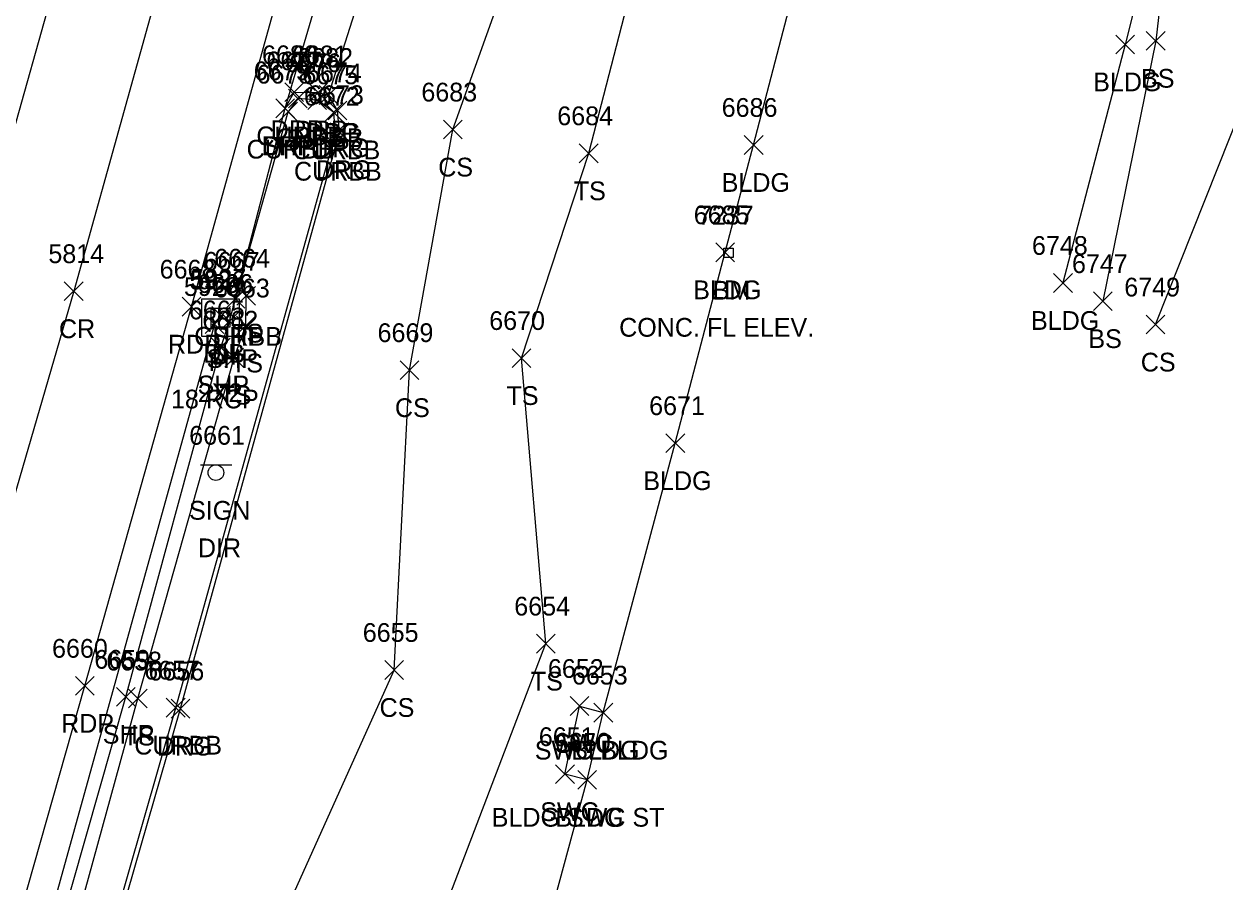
# Model space of a CAD drawing. Extents: x 1443912 to 1445411, y 621446 to 623693.
# Drawn here: x 1444716.8 to 1444844.8, y 622412.7 to 622504.3 of the extents above; entities that cross this region are included whole.
import ezdxf

# ---------------------------------------------------------------- set-up
doc = ezdxf.new("R2010")
doc.units = 0
for name, color, linetype in [('C_A', 7, 'Continuous'), ('C_I', 7, 'Continuous'), ('CPBM', 7, 'Continuous'), ('D_A', 7, 'Continuous'), ('D_C', 7, 'Continuous'), ('D_I', 7, 'Continuous'), ('D_TIC', 7, 'Continuous'), ('DCP', 7, 'Continuous'), ('DS', 7, 'Continuous'), ('L_A', 7, 'Continuous'), ('L_C', 7, 'Continuous'), ('L_I', 7, 'Continuous'), ('L_TIC', 7, 'Continuous'), ('LBC', 7, 'Continuous'), ('LELB', 7, 'Continuous'), ('P_A', 7, 'Continuous'), ('P_I', 7, 'Continuous'), ('P_TIC', 7, 'Continuous'), ('PET', 7, 'Continuous'), ('PRC', 7, 'Continuous'), ('PSP', 7, 'Continuous'), ('R_A', 7, 'Continuous'), ('R_I', 7, 'Continuous'), ('R_TIC', 7, 'Continuous'), ('RC', 7, 'Continuous'), ('RDG', 7, 'Continuous'), ('RDP', 7, 'Continuous'), ('RSW', 7, 'Continuous'), ('S_A', 7, 'Continuous'), ('S_C', 7, 'Continuous'), ('S_I', 7, 'Continuous'), ('SSGN', 7, 'Continuous')]:
    doc.layers.add(name, color=color, linetype=linetype)

msp = doc.modelspace()

# ---------------------------------------------------------------- linework, layer by layer
at = {"layer": 'CPBM'}
for p, q in [((1444791.48, 622479.37), (1444791.48, 622480.37)), ((1444791.48, 622480.37), (1444792.48, 622480.37)), ((1444791.98, 622479.87), (1444791.98, 622479.87)), ((1444791.98, 622479.87), (1444791.98, 622479.87)), ((1444792.48, 622480.37), (1444792.48, 622479.37)), ((1444792.48, 622479.37), (1444791.48, 622479.37))]:
    msp.add_line(p, q, dxfattribs=at)
at = {"layer": 'D_TIC'}
for points in [[(1444736.85, 622472.13), (1444738.85, 622474.13)], [(1444738.85, 622472.13), (1444736.85, 622474.13)], [(1444736.15, 622471.26), (1444738.15, 622473.26)], [(1444738.15, 622471.26), (1444736.15, 622473.26)]]:
    msp.add_lwpolyline(points, dxfattribs=at)
at = {"layer": 'DCP'}
msp.add_lwpolyline([(1444737.15, 622472.26), (1444683.32, 622278.32)], dxfattribs=at)
at = {"layer": 'DS'}
for p, q in [((1444735.8, 622474.94), (1444739.8, 622474.94)), ((1444735.8, 622470.94), (1444735.8, 622474.94)), ((1444739.8, 622474.94), (1444739.8, 622470.94)), ((1444736.8, 622471.94), (1444736.8, 622473.94)), ((1444736.8, 622473.94), (1444738.8, 622473.94)), ((1444738.8, 622473.94), (1444738.8, 622471.94)), ((1444737.81, 622472.94), (1444737.81, 622472.94)), ((1444737.81, 622472.94), (1444737.81, 622472.94)), ((1444739.8, 622470.94), (1444735.8, 622470.94)), ((1444738.8, 622471.94), (1444736.8, 622471.94))]:
    msp.add_line(p, q, dxfattribs=at)
at = {"layer": 'L_TIC'}
for points in [[(1444833.3, 622501.09), (1444835.3, 622503.09)], [(1444835.3, 622501.09), (1444833.3, 622503.09)], [(1444836.56, 622501.47), (1444838.56, 622503.47)], [(1444838.56, 622501.47), (1444836.56, 622503.47)], [(1444761.58, 622492), (1444763.58, 622494)], [(1444763.58, 622492), (1444761.58, 622494)], [(1444776.07, 622489.47), (1444778.07, 622491.47)], [(1444778.07, 622489.47), (1444776.07, 622491.47)], [(1444793.67, 622490.36), (1444795.67, 622492.36)], [(1444795.67, 622490.36), (1444793.67, 622492.36)], [(1444790.63, 622478.91), (1444792.63, 622480.91)], [(1444792.63, 622478.91), (1444790.63, 622480.91)], [(1444826.67, 622475.64), (1444828.67, 622477.64)], [(1444828.67, 622475.64), (1444826.67, 622477.64)], [(1444739.52, 622474.28), (1444741.52, 622476.28)], [(1444741.52, 622474.28), (1444739.52, 622476.28)], [(1444830.93, 622473.7), (1444832.93, 622475.7)], [(1444832.93, 622473.7), (1444830.93, 622475.7)], [(1444739.51, 622471.1), (1444741.51, 622473.1)], [(1444741.51, 622471.1), (1444739.51, 622473.1)], [(1444836.53, 622471.2), (1444838.53, 622473.2)], [(1444838.53, 622471.2), (1444836.53, 622473.2)], [(1444738.26, 622467.67), (1444740.26, 622469.67)], [(1444740.26, 622467.67), (1444738.26, 622469.67)], [(1444768.9, 622467.63), (1444770.9, 622469.63)], [(1444770.9, 622467.63), (1444768.9, 622469.63)], [(1444756.96, 622466.34), (1444758.96, 622468.34)], [(1444758.96, 622466.34), (1444756.96, 622468.34)], [(1444785.31, 622458.55), (1444787.31, 622460.55)], [(1444787.31, 622458.55), (1444785.31, 622460.55)], [(1444771.49, 622437.17), (1444773.49, 622439.17)], [(1444773.49, 622437.17), (1444771.49, 622439.17)], [(1444755.32, 622434.36), (1444757.32, 622436.36)], [(1444757.32, 622434.36), (1444755.32, 622436.36)], [(1444727.96, 622431.31), (1444729.96, 622433.31)], [(1444729.96, 622431.31), (1444727.96, 622433.31)], [(1444777.63, 622429.81), (1444779.63, 622431.81)], [(1444779.63, 622429.81), (1444777.63, 622431.81)], [(1444775.91, 622422.65), (1444777.91, 622424.65)], [(1444777.91, 622422.65), (1444775.91, 622424.65)]]:
    msp.add_lwpolyline(points, dxfattribs=at)
at = {"layer": 'LBC'}
msp.add_lwpolyline([(1444792.62, 622344.51), (1444758.25, 622353.56), (1444766.9, 622386.76), (1444776.91, 622423.65), (1444778.63, 622430.81), (1444786.31, 622459.55), (1444791.63, 622479.91), (1444794.67, 622491.36), (1444803.27, 622524.38), (1444837.65, 622515.4), (1444834.3, 622502.09), (1444827.67, 622476.64)], dxfattribs=at)
at = {"layer": 'LELB'}
for points in [[(1444744.93, 622339.22), (1444745.5, 622357.06), (1444753.17, 622387.48), (1444772.49, 622438.17), (1444769.9, 622468.63), (1444777.07, 622490.47), (1444785.46, 622522.85), (1444790.77, 622543.67), (1444811.19, 622567.84), (1444821.42, 622569.11), (1444823.99, 622546.92), (1444828.15, 622535.05)], [(1444742.88, 622284.71), (1444748.75, 622311.2), (1444753.94, 622334.73), (1444744.93, 622339.22), (1444726.6, 622359.05), (1444735.05, 622388.08), (1444756.32, 622435.36), (1444757.96, 622467.34), (1444762.58, 622493), (1444774.84, 622527.33), (1444774.74, 622549.75)], [(1444837.37, 622518.31), (1444839.05, 622515.22), (1444837.56, 622502.47), (1444831.93, 622474.7)], [(1444837.53, 622472.2), (1444848.13, 622498.83), (1444853.79, 622477.95)], [(1444739.97, 622249.43), (1444721.46, 622251.74), (1444700.92, 622255.52), (1444690.61, 622258.05), (1444683.65, 622264.07), (1444685.55, 622270.32), (1444689.9, 622281.11), (1444696.48, 622313.23), (1444707.7, 622344.5), (1444714.14, 622363.56), (1444716.18, 622385.71), (1444728.96, 622432.31), (1444739.26, 622468.67), (1444740.51, 622472.1), (1444740.52, 622475.28)]]:
    msp.add_lwpolyline(points, dxfattribs=at)
at = {"layer": 'P_TIC'}
for points in [[(1444743.7, 622494.27), (1444745.7, 622496.27)], [(1444745.7, 622494.27), (1444743.7, 622496.27)], [(1444721.13, 622474.76), (1444723.13, 622476.76)], [(1444723.13, 622474.76), (1444721.13, 622476.76)], [(1444733.7, 622473.11), (1444735.7, 622475.11)], [(1444735.7, 622473.11), (1444733.7, 622475.11)], [(1444738.4, 622473.95), (1444740.4, 622475.95)], [(1444740.4, 622473.95), (1444738.4, 622475.95)], [(1444737.76, 622471.58), (1444739.76, 622473.58)], [(1444739.76, 622471.58), (1444737.76, 622473.58)], [(1444736.82, 622468.76), (1444738.82, 622470.76)], [(1444738.82, 622468.76), (1444736.82, 622470.76)], [(1444722.31, 622432.67), (1444724.31, 622434.67)], [(1444724.31, 622432.67), (1444722.31, 622434.67)], [(1444726.7, 622431.5), (1444728.7, 622433.5)], [(1444728.7, 622431.5), (1444726.7, 622433.5)]]:
    msp.add_lwpolyline(points, dxfattribs=at)
at = {"layer": 'PET'}
msp.add_lwpolyline([(1444623.48, 622089.5), (1444632.2, 622118.09), (1444643.37, 622155.41), (1444656.28, 622199.74), (1444664.4, 622229.62), (1444679.43, 622278.16), (1444690.09, 622315.58), (1444698.44, 622345.72), (1444710.36, 622388.15), (1444723.31, 622433.67), (1444734.7, 622474.11), (1444754.07, 622543.94), (1444762.27, 622574.66), (1444773.16, 622611.58)], dxfattribs=at)
at = {"layer": 'PRC'}
for points in [[(1444864.1, 623005.34), (1444851.39, 622950.16), (1444837.25, 622893.61), (1444822.84, 622838.02), (1444810.34, 622792.94), (1444799.32, 622750.35), (1444788.05, 622712.65), (1444779.51, 622680.27), (1444771.55, 622651.63), (1444762.01, 622615.65), (1444752.75, 622584.12), (1444739.92, 622538.84), (1444733.6, 622516.91), (1444722.13, 622475.76), (1444713.59, 622446.41), (1444702.09, 622404.55), (1444689.87, 622361.08), (1444676.17, 622311.92), (1444657.59, 622249.98), (1444643.66, 622204.01), (1444635.38, 622177.66), (1444620.59, 622126.88), (1444604.97, 622075.74)], [(1444846.73, 622950.74), (1444829.37, 622896.11), (1444814.12, 622840.53), (1444801.7, 622795.63), (1444790.08, 622753.54), (1444778.65, 622716.11), (1444769.12, 622683.18), (1444760.94, 622654.81), (1444750.77, 622619.03), (1444741.67, 622586.01), (1444729.73, 622541.23), (1444723.42, 622520.39), (1444711.77, 622478.97), (1444703.65, 622449.63), (1444691.66, 622407.43), (1444679.51, 622365.85), (1444664.93, 622313.64), (1444649.43, 622253.98), (1444637.04, 622206.21), (1444631.31, 622178.74), (1444618.32, 622127.38), (1444604.97, 622075.74)]]:
    msp.add_lwpolyline(points, dxfattribs=at)
at = {"layer": 'PSP'}
msp.add_lwpolyline([(1444628.13, 622076.36), (1444639.3, 622115.36), (1444644.89, 622137.62), (1444649.21, 622153.55), (1444661.8, 622198.05), (1444670.3, 622227.5), (1444674.58, 622242.76), (1444679.89, 622261.63), (1444684.08, 622277.6), (1444693.94, 622313.61), (1444703.2, 622344.72), (1444709.19, 622365.83), (1444714.84, 622387.4), (1444727.7, 622432.5), (1444737.82, 622469.76), (1444738.76, 622472.58), (1444739.4, 622474.95), (1444744.7, 622495.27), (1444757.04, 622537.24), (1444773.11, 622588.76)], dxfattribs=at)
at = {"layer": 'R_TIC'}
for points in [[(1444744.66, 622495.98), (1444746.66, 622497.98)], [(1444746.66, 622495.98), (1444744.66, 622497.98)], [(1444747.21, 622495.96), (1444749.21, 622497.96)], [(1444749.21, 622495.96), (1444747.21, 622497.96)], [(1444745.03, 622495.33), (1444747.03, 622497.33)], [(1444747.03, 622495.33), (1444745.03, 622497.33)], [(1444747.11, 622495.13), (1444749.11, 622497.13)], [(1444749.11, 622495.13), (1444747.11, 622497.13)], [(1444748.33, 622495.69), (1444750.33, 622497.69)], [(1444750.33, 622495.69), (1444748.33, 622497.69)], [(1444748.33, 622495.69), (1444750.33, 622497.69)], [(1444750.33, 622495.69), (1444748.33, 622497.69)], [(1444743.7, 622494.27), (1444745.7, 622496.27)], [(1444745.7, 622494.27), (1444743.7, 622496.27)], [(1444744, 622493.91), (1444746, 622495.91)], [(1444746, 622493.91), (1444744, 622495.91)], [(1444744, 622493.91), (1444746, 622495.91)], [(1444746, 622493.91), (1444744, 622495.91)], [(1444748.88, 622493.84), (1444750.88, 622495.84)], [(1444750.88, 622493.84), (1444748.88, 622495.84)], [(1444749.28, 622494.05), (1444751.28, 622496.05)], [(1444751.28, 622494.05), (1444749.28, 622496.05)], [(1444749.05, 622491.56), (1444751.05, 622493.56)], [(1444751.05, 622491.56), (1444749.05, 622493.56)], [(1444749.49, 622491.72), (1444751.49, 622493.72)], [(1444751.49, 622491.72), (1444749.49, 622493.72)], [(1444738.4, 622473.95), (1444740.4, 622475.95)], [(1444740.4, 622473.95), (1444738.4, 622475.95)], [(1444775.08, 622430.52), (1444777.08, 622432.52)], [(1444777.08, 622430.52), (1444775.08, 622432.52)], [(1444732.01, 622430.34), (1444734.01, 622432.34)], [(1444734.01, 622430.34), (1444732.01, 622432.34)], [(1444732.52, 622430.24), (1444734.52, 622432.24)], [(1444734.52, 622430.24), (1444732.52, 622432.24)], [(1444777.63, 622429.81), (1444779.63, 622431.81)], [(1444779.63, 622429.81), (1444777.63, 622431.81)], [(1444773.54, 622423.25), (1444775.54, 622425.25)], [(1444775.54, 622423.25), (1444773.54, 622425.25)], [(1444775.91, 622422.65), (1444777.91, 622424.65)], [(1444777.91, 622422.65), (1444775.91, 622424.65)]]:
    msp.add_lwpolyline(points, dxfattribs=at)
at = {"layer": 'RC'}
for points in [[(1444717.51, 622384.77), (1444720.96, 622389.26), (1444733.01, 622431.34), (1444750.05, 622492.56), (1444749.88, 622494.84), (1444748.11, 622496.13), (1444746.03, 622496.33), (1444745, 622494.91)], [(1444739.4, 622474.95), (1444745, 622494.91)]]:
    msp.add_lwpolyline(points, dxfattribs=at)
at = {"layer": 'RDG'}
msp.add_lwpolyline([(1444714.84, 622387.4), (1444716.18, 622385.71), (1444717.51, 622384.77), (1444721.54, 622389.61), (1444733.52, 622431.24), (1444750.49, 622492.72), (1444750.28, 622495.05), (1444749.33, 622496.69)], dxfattribs=at)
at = {"layer": 'RDP'}
msp.add_lwpolyline([(1444744.7, 622495.27), (1444745.66, 622496.98), (1444748.21, 622496.96), (1444749.33, 622496.69), (1444761.59, 622535.21), (1444757.04, 622537.24)], dxfattribs=at)
at = {"layer": 'RSW'}
msp.add_lwpolyline([(1444776.91, 622423.65), (1444774.54, 622424.25), (1444776.08, 622431.52), (1444778.63, 622430.81)], dxfattribs=at)
at = {"layer": 'SSGN'}
for p, q in [((1444735.65, 622457.24), (1444738.99, 622457.24)), ((1444737.3, 622456.41), (1444737.3, 622456.41))]:
    msp.add_line(p, q, dxfattribs=at)
msp.add_circle((1444737.3, 622456.41), 0.833, dxfattribs=at)

# ---------------------------------------------------------------- texts
at = {"layer": 'C_A'}
msp.add_text('BM', height=2, dxfattribs=at).set_placement((1444790.3, 622474.87))
at = {"layer": 'C_I'}
msp.add_text('7237', height=2, dxfattribs=at).set_placement((1444788.72, 622482.87))
at = {"layer": 'D_A'}
for s, p in [('DIB', (1444735.95, 622468.13)), ('DI', (1444736.86, 622467.94)), ('P', (1444736.53, 622467.26))]:
    msp.add_text(s, height=2, dxfattribs=at).set_placement(p)
at = {"layer": 'D_C'}
for s, p in [('2X2', (1444735.38, 622463.94)), ('18 RCP', (1444732.51, 622463.26))]:
    msp.add_text(s, height=2, dxfattribs=at).set_placement(p)
at = {"layer": 'D_I'}
for s, p in [('5928', (1444733.89, 622475.26)), ('5926', (1444734.49, 622475.94)), ('5927', (1444734.59, 622476.13))]:
    msp.add_text(s, height=2, dxfattribs=at).set_placement(p)
at = {"layer": 'L_A'}
for s, p in [('BLDG', (1444830.89, 622497.09)), ('BS', (1444836, 622497.47)), ('CS', (1444761.02, 622488)), ('TS', (1444775.48, 622485.47)), ('BLDG', (1444791.26, 622486.36)), ('BLDG', (1444788.22, 622474.91)), ('BLDG', (1444824.26, 622471.64)), ('TS', (1444738.93, 622470.28)), ('BS', (1444830.38, 622469.7)), ('TS', (1444738.91, 622467.1)), ('CS', (1444835.97, 622467.2)), ('TS', (1444737.67, 622463.67)), ('TS', (1444768.31, 622463.63)), ('CS', (1444756.4, 622462.34)), ('BLDG', (1444782.9, 622454.55)), ('TS', (1444770.9, 622433.17)), ('CS', (1444754.76, 622430.36)), ('TS', (1444727.36, 622427.31)), ('BLDG', (1444775.22, 622425.81)), ('BLDG', (1444773.5, 622418.65))]:
    msp.add_text(s, height=2, dxfattribs=at).set_placement(p)
at = {"layer": 'L_C'}
msp.add_text('CONC. FL ELEV.', height=2, dxfattribs=at).set_placement((1444780.32, 622470.91))
at = {"layer": 'L_I'}
for s, p in [('6683', (1444759.22, 622496)), ('6684', (1444773.72, 622493.47)), ('6686', (1444791.26, 622494.36)), ('6685', (1444788.28, 622482.91)), ('6748', (1444824.36, 622479.64)), ('6664', (1444737.12, 622478.28)), ('6747', (1444828.63, 622477.7)), ('6663', (1444737.1, 622475.1)), ('6749', (1444834.21, 622475.2)), ('6662', (1444735.86, 622471.67)), ('6670', (1444766.46, 622471.63)), ('6669', (1444754.55, 622470.34)), ('6671', (1444783.52, 622462.55)), ('6654', (1444769.13, 622441.17)), ('6655', (1444752.97, 622438.36)), ('6658', (1444725.6, 622435.31)), ('6653', (1444775.28, 622433.81)), ('6650', (1444773.47, 622426.65))]:
    msp.add_text(s, height=2, dxfattribs=at).set_placement(p)
at = {"layer": 'P_A'}
for s, p in [('SHP', (1444742.24, 622490.27)), ('CR', (1444720.56, 622470.76)), ('RDP', (1444732.19, 622469.11)), ('SHP', (1444736.93, 622469.95)), ('SHP', (1444736.3, 622467.58)), ('SHP', (1444735.35, 622464.76)), ('RDP', (1444720.79, 622428.67)), ('SHP', (1444725.23, 622427.5))]:
    msp.add_text(s, height=2, dxfattribs=at).set_placement(p)
at = {"layer": 'P_I'}
for s, p in [('6679', (1444741.34, 622498.27)), ('5814', (1444719.43, 622478.76)), ('6667', (1444736, 622477.95)), ('6668', (1444731.3, 622477.11)), ('6666', (1444735.31, 622475.58)), ('6665', (1444734.42, 622472.76)), ('6660', (1444719.82, 622436.67)), ('6659', (1444724.33, 622435.5))]:
    msp.add_text(s, height=2, dxfattribs=at).set_placement(p)
at = {"layer": 'R_A'}
for s, p in [('DRP', (1444743.15, 622491.98)), ('DRP', (1444745.7, 622491.96)), ('CURBB', (1444741.62, 622491.33)), ('CURBB', (1444743.7, 622491.13)), ('DRG', (1444746.82, 622491.69)), ('DRP', (1444746.82, 622491.69)), ('CURBB', (1444740.58, 622489.91)), ('CURBB', (1444740.58, 622489.91)), ('DRP', (1444742.19, 622490.27)), ('CURBB', (1444745.47, 622489.84)), ('DRG', (1444747.77, 622490.05)), ('CURBB', (1444745.63, 622487.56)), ('DRG', (1444747.98, 622487.72)), ('CURBB', (1444734.98, 622469.95)), ('CURBB', (1444728.59, 622426.34)), ('DRG', (1444731.01, 622426.24)), ('SWC BLDG', (1444771.32, 622425.81)), ('SWC', (1444773.44, 622426.52)), ('SWC', (1444771.9, 622419.25)), ('BLDG SWC ST', (1444766.73, 622418.65))]:
    msp.add_text(s, height=2, dxfattribs=at).set_placement(p)
at = {"layer": 'R_I'}
for s, p in [('6680', (1444742.22, 622499.98)), ('6681', (1444745.42, 622499.96)), ('6682', (1444745.98, 622499.69)), ('6682', (1444745.98, 622499.69)), ('6679', (1444741.34, 622498.27)), ('6677', (1444742.68, 622499.33)), ('6676', (1444744.7, 622499.13)), ('6678', (1444741.64, 622497.91)), ('6678', (1444741.64, 622497.91)), ('6675', (1444746.53, 622497.84)), ('6674', (1444746.92, 622498.05)), ('6673', (1444747.13, 622495.72)), ('6672', (1444746.69, 622495.56)), ('6667', (1444736, 622477.95)), ('6657', (1444729.65, 622434.34)), ('6652', (1444772.72, 622434.52)), ('6656', (1444730.11, 622434.24)), ('6653', (1444775.28, 622433.81)), ('6651', (1444771.75, 622427.25)), ('6650', (1444773.47, 622426.65))]:
    msp.add_text(s, height=2, dxfattribs=at).set_placement(p)
at = {"layer": 'S_A'}
msp.add_text('SIGN', height=2, dxfattribs=at).set_placement((1444734.44, 622451.39))
at = {"layer": 'S_C'}
msp.add_text('DIR', height=2, dxfattribs=at).set_placement((1444735.38, 622447.39))
at = {"layer": 'S_I'}
msp.add_text('6661', height=2, dxfattribs=at).set_placement((1444734.45, 622459.39))

doc.saveas('drawing.dxf')
